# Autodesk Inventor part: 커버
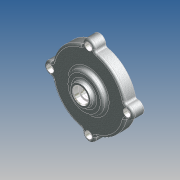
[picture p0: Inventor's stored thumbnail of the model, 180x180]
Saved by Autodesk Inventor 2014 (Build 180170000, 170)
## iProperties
Created: 2012-05
Part Number: 커버
Document SubType Name: 모델링
Designer: SeoGD™
Material: 알루미늄 6061
Appearance: 알루미늄 캐스트
Density: 2.71 g/cm^3
Mass: 196.657 g
Surface Area: 278.607 cm^2
Volume: 72.5671 cm^3
변환 표준: STEP AP214IS
파일 이름: C:\Users\SeoGD\Desktop\?쒗뿕\而ㅻ쾭-1.stp
전처리기: Build: 253, Release: 2010 SP1 - Date: Wed 07/29/2009
전송 단위: 밀리미터
불확실성: 0.01
Author: SeoGD™
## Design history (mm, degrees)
sketch "스케치1"
  geometry: L1 (0, 0)-(0, 26); L2 (50, 0)-(50, 15); L3 (50, 15)-(25, 15); L4 (25, 15)-(25, 21); L5 (25, 21)-(15, 21); L6 (15, 21)-(13.66, 26); L7 (13.66, 26)-(10, 26); L8 (50, 0)-(45, 0); L9 (45, 0)-(45, 10); L10 (45, 10)-(14.5, 10); L11 (14.5, 10)-(13.266, 3); L12 (13.266, 3)-(11, 3); L13 (11, 3)-(11, 16); L14 (11, 16)-(7.5, 16); L15 (7.5, 16)-(7.5, 19); L16 (7.5, 19)-(10, 19); L17 (10, 19)-(10, 26)
  constraints: 34 end point, 10 parallel, 2 perpendicular, 2 point on line, 1 vertical
  dimensions: "d11" = 100 diameter of L2 L1; "d12" = 22 diameter of L13 L1; "d13" = 90 diameter of L9 L1; "d14" = 15 distance between parallel lines of L3 L8; "d15" = 10 distance between parallel lines of L8 L10; "d16" = 29 diameter of L10.end L1; "d17" = 100 deg angle of L11 L10; "d18" = 7 distance between parallel lines of L12 L10; "d19" = 13 distance between parallel lines of L14 L12; "d20" = 3 distance between parallel lines of L16 L14; "d21" = 15 diameter of L15 L1; "d22" = 20 diameter of L17 L1; "d23" = 30 diameter of L5.end L1; "d24" = 6 distance between parallel lines of L5 L3; "d25" = 50 diameter of L4 L1; "d26" = 105 deg angle of L5 L6; "d50" = 26 distance of L1.start L1.end
revolve "회전1" sketch "스케치1" stored, may be unused: angle "d27" = 90 deg
sketch "스케치2" dims "d29" = 104
  geometry: A1 r 8.5 centre (0, 52) between (8.074, 49.344) and (-8.074, 49.344); A2 r 50 centre (0, 0) between (-8.074, 49.344) and (8.074, 49.344) reference; 2 further points
  constraints: 4 point on circle, 2 vertical alignment, 1 centre point, 1 coincident, 2 other
  dimensions: "d28" = 17 diameter of A1
extrude "돌출1" join sketch "스케치2" stored distance "d30" = 10; taper "d31" = 0 deg
fillet "모깎기3" dims "d32" = 3
fillet "모깎기4" dims "d45" = 3, "d46" = 0.2
chamfer "모따기1" distance "d47" = 1; stored, may be unused: second distance "d48" = 2, angle "d49" = 45 deg
hole "구멍2" diameter "d38" = 5.5; stored, may be unused: countersink angle "d42" = 90 deg, drill point angle "d44" = 118 deg; dims "d36" = 10, "d37" = 10, "d39" = 6, "d40" = 9.5, "d41" = 5.4, "d43" = 8
node "솔리드1"
node "솔리드 본체"
node "곡면 본체"
pattern_circular "원형 패턴1" dims angle "d34" = 360 deg
pattern_circular "원형 패턴2" dims angle "d52" = 360 deg
node "솔리드2"
